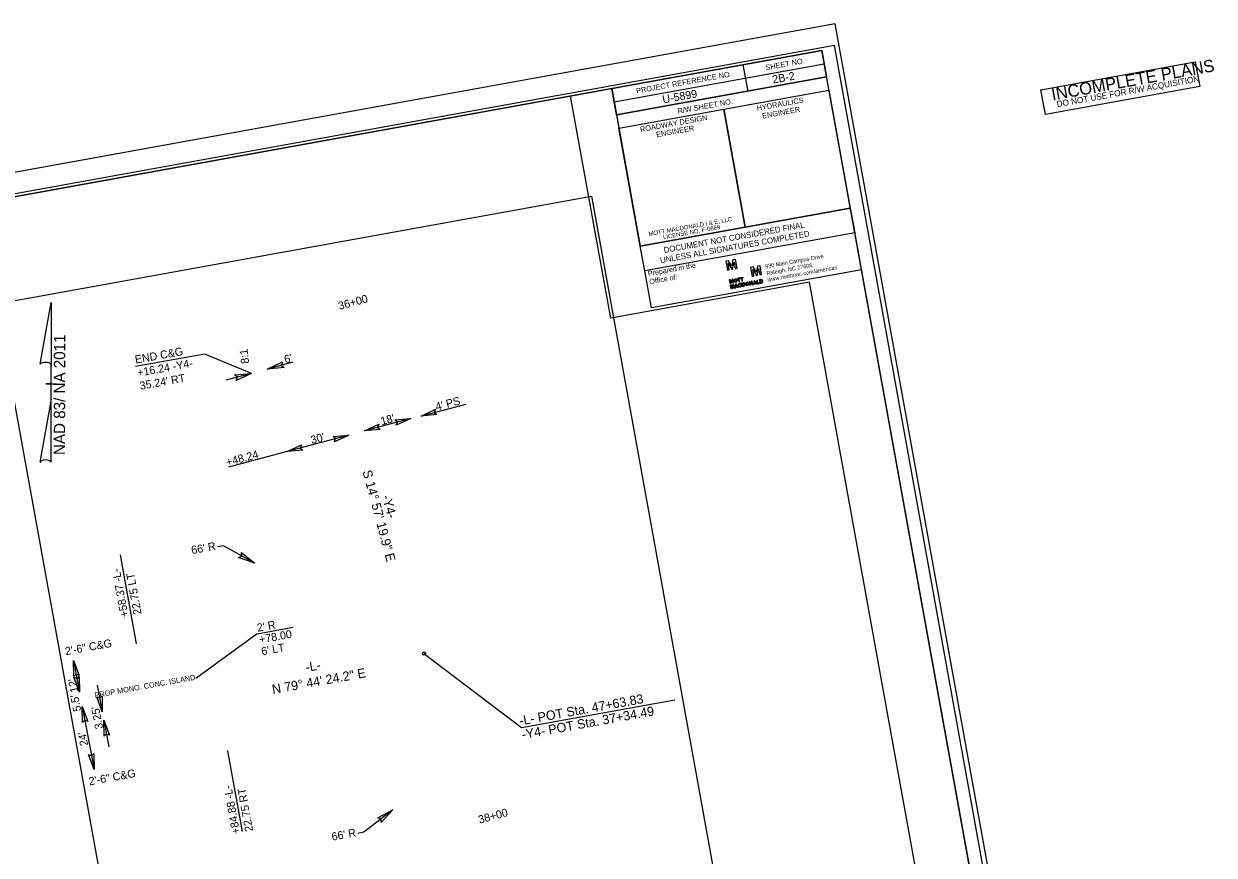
# Model space of a CAD drawing. Extents: x 1620721 to 1621526, y 897852 to 898403.
# Drawn here: x 1621079.6 to 1621525.9, y 898091.1 to 898402.8 of the extents above; entities that cross this region are included whole.
import ezdxf

# ---------------------------------------------------------------- set-up
doc = ezdxf.new("R2010")
doc.units = 0
for name, color, linetype in [('Old_Level_2', 7, 'Continuous'), ('Old_Level_42', 7, 'Continuous'), ('Old_Level_45', 7, 'Continuous'), ('Prop Conc 2ft 6in Curb and Gutter', 7, 'Continuous'), ('Prop Dimension', 7, 'Continuous'), ('Prop DSN Text', 7, 'Continuous'), ('Prop Horizontal Alignment Direction Label', 7, 'Continuous'), ('Prop Horizontal Alignment Station Label', 7, 'Continuous'), ('Prop North Arrow NAD83 for Plan Sheets CELL', 7, 'Continuous'), ('Prop Terminator CELL', 7, 'Continuous'), ('Sheet Clip Boundary CELL', 7, 'Continuous'), ('Sheet Cutting Line CELL', 7, 'Continuous'), ('Sheet Data Field CELL', 7, 'Continuous'), ('Sheet Layout Plan Border', 7, 'Continuous'), ('Sheet Plan CELL', 7, 'Continuous'), ('Sheet Plot Border Inside CELL', 7, 'Continuous'), ('Sheet Plot Border Outside CELL', 7, 'Continuous'), ('Sheet Sticker Exception Certification CELL', 7, 'Continuous'), ('Sheet Sticker Incomplete CELL', 7, 'Continuous')]:
    doc.layers.add(name, color=color, linetype=linetype)

msp = doc.modelspace()

# ---------------------------------------------------------------- linework, layer by layer
at = {"layer": 'Old_Level_2'}
for p, q in [((1621343.78, 898314), (1621342.78, 898313.82)), ((1621342.78, 898313.82), (1621343.39, 898310.47)), ((1621343.66, 898313), (1621343.67, 898313.01)), ((1621344.1, 898310.6), (1621343.66, 898313)), ((1621343.67, 898313.01), (1621345.05, 898310.77)), ((1621344.96, 898312.08), (1621343.78, 898314)), ((1621345.41, 898314.29), (1621344.98, 898312.08)), ((1621345.35, 898310.83), (1621345.86, 898313.41)), ((1621346.41, 898314.47), (1621345.41, 898314.29)), ((1621345.86, 898313.41), (1621345.87, 898313.41)), ((1621345.87, 898313.41), (1621346.31, 898311)), ((1621347.01, 898311.13), (1621346.41, 898314.47)), ((1621343.39, 898310.47), (1621344.1, 898310.6)), ((1621344.96, 898312.05), (1621344.96, 898312.08)), ((1621344.98, 898312.05), (1621344.96, 898312.05)), ((1621344.98, 898312.08), (1621344.98, 898312.05)), ((1621345.05, 898310.77), (1621345.35, 898310.83)), ((1621346.31, 898311), (1621347.01, 898311.13)), ((1621352.99, 898311.64), (1621352, 898311.46)), ((1621352, 898311.46), (1621352.6, 898308.11)), ((1621353.31, 898308.24), (1621352.87, 898310.65)), ((1621352.87, 898310.65), (1621352.88, 898310.65)), ((1621352.88, 898310.65), (1621354.26, 898308.41)), ((1621354.17, 898309.72), (1621352.99, 898311.64)), ((1621354.18, 898309.69), (1621354.17, 898309.72)), ((1621354.2, 898309.69), (1621354.18, 898309.69)), ((1621354.63, 898311.93), (1621354.19, 898309.72)), ((1621354.19, 898309.72), (1621354.2, 898309.69)), ((1621354.26, 898308.41), (1621354.57, 898308.47)), ((1621354.57, 898308.47), (1621355.07, 898311.05)), ((1621355.62, 898312.11), (1621354.63, 898311.93)), ((1621355.07, 898311.05), (1621355.08, 898311.06)), ((1621355.08, 898311.06), (1621355.52, 898308.64)), ((1621355.52, 898308.64), (1621356.22, 898308.77)), ((1621356.22, 898308.77), (1621355.62, 898312.11)), ((1621344.43, 898306.88), (1621344.05, 898306.81)), ((1621344.05, 898306.81), (1621344.28, 898305.53)), ((1621344.28, 898305.53), (1621344.55, 898305.58)), ((1621344.55, 898305.58), (1621344.38, 898306.5)), ((1621344.38, 898306.5), (1621344.39, 898306.5)), ((1621344.38, 898306.5), (1621344.39, 898306.5)), ((1621344.39, 898306.5), (1621344.92, 898305.64)), ((1621344.79, 898304.89), (1621344.41, 898304.82)), ((1621344.41, 898304.82), (1621344.64, 898303.54)), ((1621344.89, 898306.14), (1621344.43, 898306.88)), ((1621344.74, 898304.51), (1621344.75, 898304.52)), ((1621344.91, 898303.59), (1621344.74, 898304.51)), ((1621344.75, 898304.52), (1621345.28, 898303.66)), ((1621345.25, 898304.15), (1621344.79, 898304.89)), ((1621345.07, 898306.99), (1621344.89, 898306.14)), ((1621344.92, 898305.64), (1621345.04, 898305.67)), ((1621345.04, 898305.67), (1621345.23, 898306.65)), ((1621345.44, 898307.06), (1621345.07, 898306.99)), ((1621345.23, 898306.65), (1621345.24, 898306.65)), ((1621345.23, 898306.65), (1621345.24, 898306.65)), ((1621345.23, 898306.65), (1621345.24, 898306.65)), ((1621345.24, 898306.65), (1621345.41, 898305.73)), ((1621345.42, 898305.01), (1621345.25, 898304.15)), ((1621345.4, 898303.68), (1621345.59, 898304.67)), ((1621345.41, 898305.73), (1621345.68, 898305.78)), ((1621345.8, 898305.08), (1621345.42, 898305.01)), ((1621345.68, 898305.78), (1621345.44, 898307.06)), ((1621345.59, 898304.67), (1621345.6, 898304.67)), ((1621345.6, 898304.67), (1621345.77, 898303.75)), ((1621346.03, 898303.8), (1621345.8, 898305.08)), ((1621348.37, 898305.11), (1621348.58, 898305.25)), ((1621348.67, 898304.55), (1621348.43, 898304.61)), ((1621349.28, 898305.7), (1621348.7, 898305.6)), ((1621348.7, 898305.6), (1621348.82, 898304.94)), ((1621348.82, 898304.94), (1621348.93, 898304.32)), ((1621348.93, 898304.32), (1621349.51, 898304.43)), ((1621349.01, 898305.41), (1621349.32, 898305.47)), ((1621349.15, 898304.61), (1621349.01, 898305.41)), ((1621349.47, 898304.67), (1621349.15, 898304.61)), ((1621352.6, 898308.11), (1621353.31, 898308.24)), ((1621355.9, 898306.9), (1621355.32, 898306.8)), ((1621355.32, 898306.8), (1621355.32, 898306.8)), ((1621355.32, 898306.8), (1621355.44, 898306.13)), ((1621355.44, 898306.13), (1621355.55, 898305.52)), ((1621355.55, 898305.52), (1621356.13, 898305.62)), ((1621355.63, 898306.61), (1621355.94, 898306.67)), ((1621355.77, 898305.81), (1621355.63, 898306.61)), ((1621356.09, 898305.87), (1621355.77, 898305.81)), ((1621355.95, 898306.66), (1621355.95, 898306.66)), ((1621344.64, 898303.54), (1621344.91, 898303.59)), ((1621345.28, 898303.66), (1621345.4, 898303.68)), ((1621345.77, 898303.75), (1621346.03, 898303.8))]:
    msp.add_line(p, q, dxfattribs=at)
for points in [[(1621346.19, 898303.82), (1621346.49, 898303.88), (1621346.54, 898304.11), (1621347.09, 898304.21), (1621347.21, 898304.01), (1621347.51, 898304.06), (1621346.79, 898305.25), (1621346.45, 898305.19), (1621346.19, 898303.82)], [(1621346.57, 898304.36), (1621346.67, 898304.95), (1621346.98, 898304.43), (1621346.57, 898304.36)], [(1621347.09, 898307.12), (1621347.46, 898307.18), (1621347.65, 898306.14), (1621347.93, 898306.19), (1621347.74, 898307.23), (1621348.11, 898307.3), (1621348.06, 898307.53), (1621347.05, 898307.35), (1621347.09, 898307.12)], [(1621348.27, 898307.33), (1621348.64, 898307.4), (1621348.83, 898306.35), (1621349.1, 898306.4), (1621348.91, 898307.45), (1621349.28, 898307.51), (1621349.24, 898307.75), (1621348.23, 898307.56), (1621348.27, 898307.33)], [(1621351.91, 898305.72), (1621351.92, 898305.72), (1621352.69, 898305), (1621352.94, 898305.05), (1621352.71, 898306.33), (1621352.44, 898306.28), (1621352.59, 898305.47), (1621351.84, 898306.17), (1621351.57, 898306.12), (1621351.81, 898304.84), (1621352.06, 898304.89), (1621351.91, 898305.72)], [(1621353.1, 898305.08), (1621353.41, 898305.13), (1621353.45, 898305.36), (1621354.01, 898305.46), (1621354.13, 898305.26), (1621354.42, 898305.32), (1621353.7, 898306.5), (1621353.36, 898306.44), (1621353.1, 898305.08)], [(1621353.48, 898305.61), (1621353.59, 898306.2), (1621353.89, 898305.68), (1621353.48, 898305.61)], [(1621355.4, 898305.49), (1621355.36, 898305.72), (1621354.8, 898305.62), (1621354.61, 898306.67), (1621354.35, 898306.62), (1621354.58, 898305.34), (1621355.4, 898305.49)]]:
    msp.add_lwpolyline(points, dxfattribs=at)
msp.add_arc((1621356.02, 898306.26), 0.65, 280.2599, 100.2599, dxfattribs=at)
for centre, major_axis, ratio in [((1621346.43, 898306.58), (-0.116, 0.639), 0.993118), ((1621346.43, 898306.58), (-0.075, 0.417), 0.916103), ((1621350.83, 898305.32), (-0.116, 0.639), 0.993118), ((1621350.83, 898305.32), (-0.075, 0.417), 0.916103)]:
    msp.add_ellipse(centre, major_axis=major_axis, ratio=ratio, dxfattribs=at)
for centre, major_axis, ratio, start_param, end_param in [((1621348.09, 898304.83), (-0.116, 0.639), 0.993118, 5.246647, 10.366427), ((1621348.09, 898304.83), (-0.075, 0.417), 0.916103, 5.276876, 10.296021), ((1621349.4, 898305.06), (0.116, -0.639), 0.930276, 0, 3.141593), ((1621349.4, 898305.07), (0.072, -0.399), 0.900832, 0, 3.141593), ((1621356.02, 898306.27), (0.072, -0.399), 0.900832, 0, 3.141593)]:
    msp.add_ellipse(centre, major_axis=major_axis, ratio=ratio, start_param=start_param, end_param=end_param, dxfattribs=at)
at = {"layer": 'Old_Level_42'}
msp.add_lwpolyline([(1621393.62, 898310.54), (1621314.88, 898296.29), (1621312.36, 898310.18)], dxfattribs=at)
at = {"layer": 'Prop Conc 2ft 6in Curb and Gutter'}
for p, q in [((1621147.46, 898279.01), (1621121.42, 898274.3)), ((1621165.01, 898271.76), (1621147.46, 898279.01)), ((1621115.73, 898203.72), (1621121.78, 898170.3)), ((1621167.03, 898174.14), (1621180.62, 898176.6)), ((1621167.03, 898174.14), (1621144.08, 898157.32)), ((1621155.97, 898130.25), (1621161.44, 898100.03))]:
    msp.add_line(p, q, dxfattribs=at)
at = {"layer": 'Prop Dimension'}
for p, q in [((1621180.46, 898275.89), (1621170.8, 898273.31)), ((1621165.01, 898271.76), (1621155.35, 898269.17)), ((1621245.29, 898260.12), (1621228.58, 898255.65)), ((1621224.66, 898254.82), (1621207.27, 898250.17)), ((1621201.48, 898248.62), (1621178.28, 898242.43)), ((1621178.28, 898242.43), (1621156.37, 898236.57)), ((1621154.51, 898207.15), (1621152.22, 898206.74)), ((1621166.18, 898200.57), (1621154.51, 898207.15)), ((1621098.26, 898164.05), (1621100.49, 898152.22)), ((1621107.15, 898154.84), (1621109.03, 898144.87)), ((1621101.51, 898146.82), (1621105.96, 898123.27)), ((1621109.63, 898141.68), (1621111.51, 898131.74)), ((1621217.93, 898108.15), (1621207.13, 898099.71)), ((1621207.13, 898099.71), (1621204.85, 898099.29))]:
    msp.add_line(p, q, dxfattribs=at)
at = {"layer": 'Prop DSN Text'}
msp.add_lwpolyline([(1621069.41, 898297.84), (1621292.41, 898338.21), (1621348.65, 898027.48), (1621125.66, 897987.11)], close=True, dxfattribs=at)
at = {"layer": 'Prop Horizontal Alignment Station Label'}
for p, q in [((1621229.61, 898166.7), (1621266.14, 898138.98)), ((1621266.14, 898138.98), (1621323.67, 898149.39))]:
    msp.add_line(p, q, dxfattribs=at)
msp.add_circle((1621229.61, 898166.7), 0.6, dxfattribs=at)
at = {"layer": 'Prop North Arrow NAD83 for Plan Sheets CELL'}
for p, q in [((1621085.71, 898275.15), (1621089.82, 898298.32)), ((1621089.84, 898298.32), (1621089.82, 898298.32)), ((1621089.84, 898298.32), (1621089.82, 898298.32)), ((1621089.84, 898298.32), (1621089.84, 898274.42)), ((1621089.83, 898262.02), (1621089.84, 898275.12)), ((1621089.84, 898274.42), (1621089.84, 898275.1)), ((1621087.83, 898267.82), (1621087.81, 898267.82)), ((1621089.61, 898267.82), (1621087.83, 898267.82)), ((1621087.86, 898267.82), (1621091.86, 898267.82)), ((1621089.83, 898262.02), (1621085.65, 898238.4)), ((1621089.85, 898238.5), (1621089.83, 898262.02))]:
    msp.add_line(p, q, dxfattribs=at)
for centre, start_param, end_param in [((1621087.78, 898274.9), 0.216388, 2.908219), ((1621087.77, 898238.31), 0.201328, 3.141593)]:
    msp.add_ellipse(centre, major_axis=(2.11, -0.02), ratio=0.461098, start_param=start_param, end_param=end_param, dxfattribs=at)
at = {"layer": 'Prop Terminator CELL'}
for points in [[(1621177.17, 898273.89), (1621170.8, 898273.31), (1621176.63, 898276.03), (1621176.15, 898274.74)], [(1621158.64, 898271.18), (1621165.01, 898271.76), (1621159.17, 898269.04), (1621159.66, 898270.33)], [(1621234.47, 898256.36), (1621228.58, 898255.65), (1621233.92, 898258.33), (1621233.5, 898257.12)], [(1621213.18, 898250.71), (1621207.27, 898250.17), (1621212.68, 898252.69), (1621212.23, 898251.5)], [(1621218.75, 898254.28), (1621224.66, 898254.82), (1621219.24, 898252.29), (1621219.7, 898253.49)], [(1621195.56, 898248.09), (1621201.48, 898248.62), (1621196.06, 898246.1), (1621196.51, 898247.3)], [(1621184.2, 898242.97), (1621178.28, 898242.43), (1621183.7, 898244.95), (1621183.25, 898243.75)], [(1621161.22, 898204.61), (1621166.18, 898200.57), (1621160.11, 898202.7), (1621161.36, 898203.28)], [(1621098.35, 898158.11), (1621098.26, 898164.05), (1621100.37, 898158.46), (1621099.21, 898159)], [(1621100.4, 898158.16), (1621100.49, 898152.22), (1621098.38, 898157.81), (1621099.54, 898157.27)], [(1621108.93, 898150.81), (1621109.03, 898144.87), (1621106.91, 898150.46), (1621108.08, 898149.92)], [(1621101.61, 898140.88), (1621101.51, 898146.82), (1621103.62, 898141.23), (1621102.46, 898141.77)], [(1621109.73, 898135.74), (1621109.63, 898141.68), (1621111.74, 898136.09), (1621110.58, 898136.63)], [(1621105.86, 898129.21), (1621105.96, 898123.27), (1621103.84, 898128.86), (1621105, 898128.32)], [(1621212.3, 898105.12), (1621217.93, 898108.15), (1621213.63, 898103.37), (1621213.57, 898104.74)]]:
    msp.add_lwpolyline(points, close=True, dxfattribs=at)
at = {"layer": 'Sheet Clip Boundary CELL'}
msp.add_lwpolyline([(1620882.81, 897876.15), (1621433.86, 897975.9), (1621374.12, 898305.94), (1621299.62, 898292.45), (1621284.56, 898375.7), (1620808, 898289.43)], close=True, dxfattribs=at)
at = {"layer": 'Sheet Cutting Line CELL'}
msp.add_line((1621383.82, 898402.8), (1620721.19, 898282.86), dxfattribs=at)
at = {"layer": 'Sheet Layout Plan Border'}
msp.add_lwpolyline([(1620882.81, 897876.15), (1621433.86, 897975.9), (1621374.12, 898305.94), (1621299.62, 898292.45), (1621284.56, 898375.7), (1620808, 898289.43)], close=True, dxfattribs=at)
at = {"layer": 'Sheet Plan CELL'}
for p, q in [((1621300.88, 898373.55), (1621379.62, 898387.8)), ((1621349.2, 898387.37), (1621351, 898377.53)), ((1621301.78, 898368.62), (1621380.51, 898382.88)), ((1621301.78, 898368.62), (1621380.51, 898382.88)), ((1621301.78, 898368.62), (1621302.67, 898363.7)), ((1621342.05, 898370.83), (1621350.07, 898326.57))]:
    msp.add_line(p, q, dxfattribs=at)
for points in [[(1621378.74, 898392.74), (1620788.32, 898285.87), (1620863.13, 897872.59), (1621453.54, 897979.46)], [(1621299.99, 898378.49), (1621378.74, 898392.74), (1621380.51, 898382.88), (1621301.78, 898368.62)], [(1620863.13, 897872.59), (1620788.31, 898285.86), (1621299.99, 898378.49), (1621310.69, 898319.43), (1621389.42, 898333.68), (1621453.54, 897979.46)], [(1621342.05, 898370.83), (1621381.4, 898377.96), (1621389.42, 898333.68), (1621350.06, 898326.55)], [(1621302.67, 898363.7), (1621342.05, 898370.83), (1621350.06, 898326.55), (1621310.69, 898319.43)]]:
    msp.add_lwpolyline(points, close=True, dxfattribs=at)
at = {"layer": 'Sheet Plot Border Inside CELL'}
msp.add_lwpolyline([(1620802.89, 897860.66), (1621458.63, 897979.36), (1621383.47, 898394.61), (1620727.73, 898275.92)], close=True, dxfattribs=at)
at = {"layer": 'Sheet Plot Border Outside CELL'}
msp.add_lwpolyline([(1620799.2, 897851.87), (1621461.84, 897971.81), (1621383.82, 898402.8), (1620721.19, 898282.86)], close=True, dxfattribs=at)
at = {"layer": 'Sheet Sticker Exception Certification CELL'}
for p, q in [((1621310.69, 898319.43), (1621389.42, 898333.68)), ((1621310.69, 898319.43), (1621389.42, 898333.68)), ((1621389.42, 898333.68), (1621391.1, 898324.43)), ((1621389.42, 898333.68), (1621391.1, 898324.43)), ((1621391.1, 898324.43), (1621312.36, 898310.18)), ((1621391.1, 898324.43), (1621312.36, 898310.18)), ((1621312.36, 898310.18), (1621310.69, 898319.43)), ((1621312.36, 898310.18), (1621310.69, 898319.43))]:
    msp.add_line(p, q, dxfattribs=at)
at = {"layer": 'Sheet Sticker Incomplete CELL'}
msp.add_lwpolyline([(1621462.6, 898368.77), (1621460.92, 898378.02), (1621518.78, 898388.49), (1621520.46, 898379.24)], close=True, dxfattribs=at)

# ---------------------------------------------------------------- texts
at = {"layer": 'Old_Level_2'}
for s, height, p in [('Prepared in the ', 1.9274, (1621313.76, 898308.2)), ('930 Main Campus Drive', 1.5, (1621357.68, 898311.06)), ('Raleigh, NC 27606', 1.5, (1621358.14, 898308.52)), ('Office of:', 1.927, (1621314.31, 898305.15)), ('www.mottmac.com/americas', 1.5, (1621358.57, 898306.12))]:
    msp.add_text(s, height=height, rotation=10.2599, dxfattribs=at).set_placement(p)
at = {"layer": 'Old_Level_45'}
for s, p in [('MOTT MACDONALD I & E, LLC', (1621313.97, 898323.21)), (' LICENSE NO. F-0669', (1621318.83, 898321.91))]:
    msp.add_text(s, height=1.6071, rotation=10.2599, dxfattribs=at).set_placement(p)
at = {"layer": 'Prop Conc 2ft 6in Curb and Gutter'}
for s, rotation, p in [('END C&G', 10.2599, (1621121.53, 898275.4)), ('+16.24 -Y4-', 10.2599, (1621122.42, 898270.48)), ("35.24' RT", 10.2599, (1621123.31, 898265.56)), ('+58.37 -L-', 100.2581, (1621118.84, 898180.65)), ('22.75 LT', 100.2581, (1621123.76, 898181.54)), ("2' R", 10.2599, (1621167.31, 898174.88)), ('+78.00', 10.2599, (1621168.11, 898170.46)), ("6' LT", 10.2599, (1621168.91, 898166.03)), ('+84.88 -L-', 100.2599, (1621160.67, 898099.34)), ('22.75 RT', 100.2599, (1621165.59, 898100.23))]:
    msp.add_text(s, height=3, rotation=rotation, dxfattribs=at).set_placement(p)
at = {"layer": 'Prop Dimension'}
for s, height, rotation, p in [('8:1', 3, 96.7692, (1621164.09, 898275.54)), ("6'", 3, 14.9833, (1621177.66, 898275.46)), ("4' PS", 3, 14.9555, (1621234.34, 898257.75)), ("18'", 3, 14.9555, (1621213.81, 898252.3)), ("30'", 3, 14.9555, (1621187.59, 898245.27)), ('+48.24', 3, 14.9555, (1621155.86, 898236.92)), ("66' R", 3, 10.2599, (1621142.65, 898203.98)), ('2\'-6" C&G', 3, 10.3795, (1621095.33, 898166.06)), ("12'", 3, 100.6893, (1621100.06, 898152.4)), ('PROP MONO. CONC. ISLAND', 2, 10.2616, (1621106.31, 898150.08)), ("5.5'", 3, 100.6893, (1621101.12, 898145.25)), ("3.25'", 3, 100.6893, (1621109.34, 898138.68)), ("24'", 3, 100.6893, (1621103.73, 898132.35)), ('2\'-6" C&G', 3, 10.3795, (1621104.23, 898117.28)), ("66' R", 3, 10.2599, (1621195.27, 898096.54))]:
    msp.add_text(s, height=height, rotation=rotation, dxfattribs=at).set_placement(p)
at = {"layer": 'Prop Horizontal Alignment Direction Label'}
for s, rotation, p in [('S 14%%d 57\' 19.9" E', 284.9555, (1621206.53, 898235.03)), ('-Y4-', 284.9555, (1621213.86, 898225.63)), ('N 79%%d 44\' 24.2" E', 10.2599, (1621172.98, 898151.51)), ('-L-', 10.2599, (1621185.5, 898159.78))]:
    msp.add_text(s, height=3.5, rotation=rotation, dxfattribs=at).set_placement(p)
at = {"layer": 'Prop Horizontal Alignment Station Label'}
for s, height, rotation, p in [('36+00', 3, 14.985, (1621197.94, 898295.53)), ('-L- POT Sta. 47+63.83', 3.5, 10.2599, (1621265.68, 898139.75)), ('-Y4- POT Sta. 37+34.49', 3.5, 10.2599, (1621266.61, 898134.58)), ('38+00', 3, 14.985, (1621250.45, 898102.92))]:
    msp.add_text(s, height=height, rotation=rotation, dxfattribs=at).set_placement(p)
at = {"layer": 'Prop North Arrow NAD83 for Plan Sheets CELL'}
msp.add_text('NAD 83/ NA 2011', height=4.25, rotation=89.9808, dxfattribs=at).set_placement((1621095.09, 898241.14))
at = {"layer": 'Sheet Data Field CELL'}
for s, p in [('2B-2', (1621360.52, 898380.4)), ('U-5899', (1621319.3, 898372.91))]:
    msp.add_text(s, height=3, rotation=10.26, dxfattribs=at).set_placement(p)
at = {"layer": 'Sheet Plan CELL'}
for s, p in [('SHEET NO.', (1621357.84, 898385.37)), ('PROJECT REFERENCE NO.', (1621309.35, 898376.64)), ('R/W SHEET NO.', (1621324.87, 898369.06)), ('HYDRAULICS', (1621354.56, 898370.14)), ('ENGINEER', (1621356.6, 898367.27)), ('ROADWAY DESIGN', (1621310.81, 898362.21)), ('ENGINEER', (1621316.86, 898360.24))]:
    msp.add_text(s, height=2, rotation=10.26, dxfattribs=at).set_placement(p)
at = {"layer": 'Sheet Sticker Exception Certification CELL'}
for s, p in [('DOCUMENT NOT CONSIDERED FINAL', (1621319.72, 898316.86)), ('DOCUMENT NOT CONSIDERED FINAL', (1621319.72, 898316.86)), ('UNLESS ALL SIGNATURES COMPLETED', (1621318.35, 898313.03)), ('UNLESS ALL SIGNATURES COMPLETED', (1621318.35, 898313.03))]:
    msp.add_text(s, height=2.2, rotation=10.2599, dxfattribs=at).set_placement(p)
at = {"layer": 'Sheet Sticker Incomplete CELL'}
for s, height, p in [('INCOMPLETE PLANS', 4.608, (1621465.28, 898374.01)), ('DO NOT USE FOR R/W ACQUISITION', 2.304, (1621467.06, 898371.51))]:
    msp.add_text(s, height=height, rotation=10.2599, dxfattribs=at).set_placement(p)

doc.saveas('drawing.dxf')
